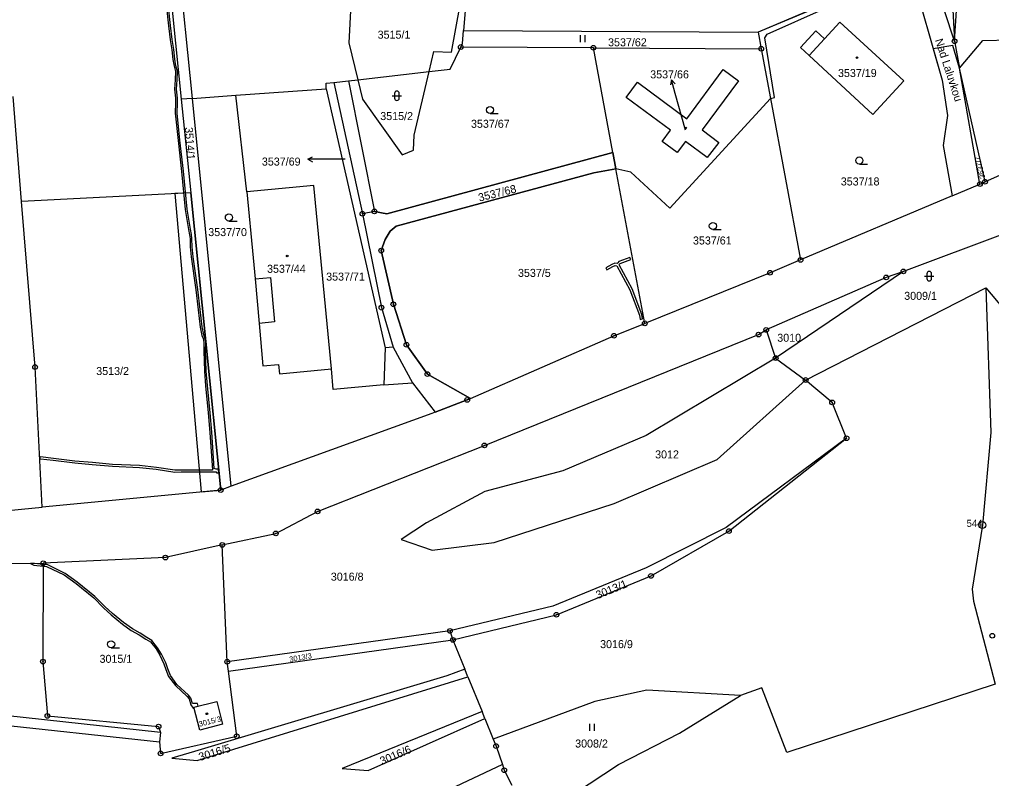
# Model space of a CAD drawing. Extents: x -644096 to -634268, y -1141430 to -1133463.
# Drawn here: x -641396.2 to -641189.8, y -1138498.2 to -1138337.1 of the extents above; entities that cross this region are included whole.
import ezdxf

# ---------------------------------------------------------------- set-up
doc = ezdxf.new("R2010")
doc.units = 0
for name, color, linetype in [('_CIVIL_CONSTRUCTION', 7, 'Continuous'), ('B_Hranice _3D', 7, 'Continuous'), ('M_Svah_Nasyp', 7, 'Continuous'), ('M_Svah_Zarez', 7, 'Continuous'), ('svrsek_osa_sjezdy', 7, 'Continuous'), ('svrsek_osa_VRT', 7, 'Continuous'), ('svrsek_popisy_VRT', 7, 'Continuous'), ('terminal_VRT', 7, 'Continuous')]:
    doc.layers.add(name, color=color, linetype=linetype)

msp = doc.modelspace()

# ---------------------------------------------------------------- linework, layer by layer
at = {"layer": '_CIVIL_CONSTRUCTION'}
for centre, radius in [((-641302.47, -1138342.92), 0.5), ((-641302.47, -1138342.92), 0.0303), ((-641274.31, -1138343.08), 0.5), ((-641274.31, -1138343.08), 0.0303), ((-641238.67, -1138343.28), 0.5), ((-641197.59, -1138341.7), 0.5), ((-641197.59, -1138341.7), 0.0303), ((-641238.67, -1138343.28), 0.0303), ((-641192.21, -1138372.01), 0.5), ((-641192.21, -1138372.01), 0.0303), ((-641191.13, -1138371.53), 0.5), ((-641191.13, -1138371.53), 0.0303), ((-641323.37, -1138378.31), 0.5), ((-641320.81, -1138377.82), 0.5), ((-641320.81, -1138377.82), 0.0303), ((-641323.37, -1138378.31), 0.0303), ((-641319.36, -1138386.15), 0.5), ((-641319.36, -1138386.15), 0.0303), ((-641230.32, -1138388.1), 0.5), ((-641230.32, -1138388.1), 0.0303), ((-641236.79, -1138390.83), 0.5), ((-641208.47, -1138390.55), 0.5), ((-641208.47, -1138390.55), 0.0303), ((-641236.79, -1138390.83), 0.0303), ((-641212.13, -1138391.83), 0.5), ((-641212.13, -1138391.83), 0.0303), ((-641319.32, -1138398.25), 0.5), ((-641319.32, -1138398.25), 0.0303), ((-641316.79, -1138397.53), 0.5), ((-641316.79, -1138397.53), 0.0303), ((-641263.4, -1138401.58), 0.5), ((-641263.4, -1138401.58), 0.0303), ((-641237.61, -1138402.96), 0.5), ((-641237.61, -1138402.96), 0.0303), ((-641269.94, -1138404.22), 0.5), ((-641269.94, -1138404.22), 0.0303), ((-641239.24, -1138403.97), 0.5), ((-641239.24, -1138403.97), 0.0303), ((-641314.01, -1138406.13), 0.5), ((-641314.01, -1138406.13), 0.0303), ((-641235.6, -1138408.96), 0.5), ((-641235.6, -1138408.96), 0.0303), ((-641392.88, -1138410.85), 0.5), ((-641392.88, -1138410.85), 0.0303), ((-641309.56, -1138412.35), 0.5), ((-641309.56, -1138412.35), 0.0303), ((-641229.23, -1138413.61), 0.5), ((-641229.23, -1138413.61), 0.0303), ((-641301.1, -1138417.82), 0.5), ((-641301.1, -1138417.82), 0.0303), ((-641223.6, -1138418.36), 0.5), ((-641223.6, -1138418.36), 0.0303), ((-641220.55, -1138425.96), 0.5), ((-641297.45, -1138427.5), 0.5), ((-641297.45, -1138427.5), 0.0303), ((-641220.55, -1138425.96), 0.0303), ((-641353.45, -1138436.97), 0.5), ((-641353.45, -1138436.97), 0.0303), ((-641332.89, -1138441.49), 0.5), ((-641332.89, -1138441.49), 0.0303), ((-641191.7, -1138444.4), 0.75), ((-641341.76, -1138446.18), 0.5), ((-641341.76, -1138446.18), 0.0303), ((-641245.52, -1138445.68), 0.5), ((-641245.52, -1138445.68), 0.0303), ((-641191.7, -1138444.4), 0.03), ((-641353.13, -1138448.62), 0.5), ((-641353.13, -1138448.62), 0.0303), ((-641391.14, -1138452.52), 0.5), ((-641391.14, -1138452.52), 0.0303), ((-641365.18, -1138451.31), 0.5), ((-641365.18, -1138451.31), 0.0303), ((-641262.07, -1138455.18), 0.5), ((-641262.07, -1138455.18), 0.0303), ((-641282.17, -1138463.44), 0.5), ((-641282.17, -1138463.44), 0.0303), ((-641304.77, -1138466.88), 0.5), ((-641304.77, -1138466.88), 0.0303), ((-641304.14, -1138468.78), 0.5), ((-641304.14, -1138468.78), 0.0303), ((-641189.59, -1138467.89), 0.5), ((-641391.2, -1138473.39), 0.5), ((-641352.07, -1138473.42), 0.5), ((-641391.2, -1138473.39), 0.0303), ((-641352.07, -1138473.42), 0.0303), ((-641390.26, -1138484.92), 0.5), ((-641390.26, -1138484.92), 0.0303), ((-641366.66, -1138487.18), 0.5), ((-641366.66, -1138487.18), 0.0303), ((-641350.05, -1138489.21), 0.5), ((-641350.05, -1138489.21), 0.0303), ((-641294.98, -1138491.33), 0.5), ((-641294.98, -1138491.33), 0.0303), ((-641366.22, -1138492.87), 0.5), ((-641366.22, -1138492.87), 0.0303), ((-641293.23, -1138496.43), 0.5), ((-641293.23, -1138496.43), 0.0303)]:
    msp.add_circle(centre, radius, dxfattribs=at)
at = {"layer": 'B_Hranice _3D'}
for points in [[(-641364.97, -1138334.51), (-641364.53, -1138338.41), (-641364.18, -1138341.38), (-641363.82, -1138343.53), (-641363.62, -1138345.54), (-641363.35, -1138347.02), (-641363.04, -1138348.15), (-641363.13, -1138349.88), (-641363.26, -1138351.89), (-641363.05, -1138353.81), (-641363.05, -1138354.74), (-641363.12, -1138356.99), (-641362.5, -1138362.77), (-641361.79, -1138369.35), (-641360.97, -1138377.42), (-641360.3, -1138381.65), (-641360.06, -1138382.76), (-641359.96, -1138383.64), (-641359.93, -1138385.35), (-641359.73, -1138387.47), (-641358.72, -1138394.44), (-641358.22, -1138398.69), (-641357.79, -1138402.37), (-641357.45, -1138404.15), (-641357.18, -1138404.77), (-641357.03, -1138405.64), (-641357.06, -1138407.4), (-641356.93, -1138411.76), (-641356.66, -1138414.83), (-641356.09, -1138420.59), (-641355.74, -1138424.72), (-641355.2, -1138432.73), (-641361.83, -1138432.71), (-641363.19, -1138432.76), (-641367.1, -1138432.16), (-641370.68, -1138431.77), (-641376.43, -1138431.52), (-641380.71, -1138431.15), (-641384.4, -1138430.8), (-641388.97, -1138430.25), (-641391.75, -1138429.89), (-641391.9, -1138429.97), (-641391.88, -1138430.43), (-641391.69, -1138430.31), (-641389.01, -1138430.65), (-641384.44, -1138431.2), (-641380.75, -1138431.55), (-641376.45, -1138431.92), (-641370.72, -1138432.17), (-641367.16, -1138432.56), (-641363.21, -1138433.16), (-641361.83, -1138433.11), (-641354.36, -1138433.13), (-641354.33, -1138433.34), (-641353.82, -1138433.32), (-641353.9, -1138432.51), (-641354.45, -1138432.55), (-641354.83, -1138432.41)], [(-641354.83, -1138432.41), (-641355.34, -1138424.68), (-641355.69, -1138420.55), (-641356.26, -1138414.79), (-641356.53, -1138411.74), (-641356.66, -1138407.4), (-641356.63, -1138405.6), (-641356.8, -1138404.65), (-641357.07, -1138404.03), (-641357.39, -1138402.31), (-641357.82, -1138398.65), (-641358.32, -1138394.38), (-641359.33, -1138387.43), (-641359.53, -1138385.33), (-641359.56, -1138383.62), (-641359.66, -1138382.7), (-641359.9, -1138381.57), (-641360.57, -1138377.36), (-641361.39, -1138369.31), (-641362.1, -1138362.73), (-641362.72, -1138356.97), (-641362.65, -1138354.74), (-641362.65, -1138353.79), (-641362.86, -1138351.89), (-641362.73, -1138349.9), (-641362.64, -1138348.11), (-641362.95, -1138346.94), (-641363.22, -1138345.48), (-641363.42, -1138343.47), (-641363.78, -1138341.32), (-641364.13, -1138338.37), (-641364.57, -1138334.47)]]:
    msp.add_lwpolyline(points, dxfattribs=at)
for points in [[(-641225.41, -1138333.93), (-641239.32, -1138339.79), (-641238.67, -1138343.28), (-641236.71, -1138353.82), (-641235.85, -1138353.67), (-641237.92, -1138340.99), (-641237.43, -1138340.2), (-641224.98, -1138334.7)], [(-641202.12, -1138343.31), (-641200.22, -1138349.93), (-641199.11, -1138357.49), (-641200.01, -1138363.84), (-641198.13, -1138374.51), (-641192.21, -1138372.01), (-641196.58, -1138347.41), (-641197.94, -1138342.57)], [(-641307.93, -1138420.4), (-641301.1, -1138417.82), (-641300.41, -1138417.52), (-641309.56, -1138412.35), (-641314.01, -1138406.13), (-641316.79, -1138397.53), (-641319.36, -1138386.15), (-641318.5, -1138383.8), (-641317.46, -1138382.02), (-641316.16, -1138380.95), (-641274.21, -1138369.64), (-641269.51, -1138368.81), (-641270.16, -1138365.31), (-641318.15, -1138378.31), (-641320.81, -1138377.82), (-641323.37, -1138378.31), (-641319.32, -1138398.25), (-641316.82, -1138406.62), (-641312.73, -1138414.18)], [(-641353.45, -1138436.97), (-641359.82, -1138373.85), (-641363.23, -1138374.03), (-641357.62, -1138437.37)], [(-641264.35, -1138400.73), (-641263.85, -1138400.65), (-641264.01, -1138399.72), (-641266.1, -1138394.27), (-641268.85, -1138389.17), (-641268.76, -1138389.02), (-641268.62, -1138388.9), (-641266.37, -1138388.03), (-641266.55, -1138387.57), (-641268.88, -1138388.46), (-641269.14, -1138388.7), (-641269.26, -1138388.88), (-641269.74, -1138388.79), (-641270.41, -1138389.08), (-641271.69, -1138389.8), (-641271.45, -1138390.23), (-641270.19, -1138389.53), (-641269.68, -1138389.31), (-641269.3, -1138389.38), (-641266.56, -1138394.48), (-641264.49, -1138399.86)], [(-641393.82, -1138452.54), (-641393.14, -1138452.93), (-641391.14, -1138453.14), (-641391.14, -1138452.74), (-641393.02, -1138452.55), (-641393.05, -1138452.53)], [(-641359.44, -1138482.3), (-641359.8, -1138481.12), (-641360.26, -1138480.5), (-641362.77, -1138478.21), (-641364.15, -1138476.36), (-641364.71, -1138474.93), (-641365.14, -1138473.67), (-641366.03, -1138471.81), (-641366.87, -1138470.43), (-641368.11, -1138468.88), (-641369.11, -1138468.26), (-641370.54, -1138467.34), (-641372.22, -1138466.46), (-641374.09, -1138465.1), (-641376.44, -1138463.14), (-641378.06, -1138461.68), (-641380.16, -1138459.56), (-641383.92, -1138456.49), (-641386.52, -1138454.65), (-641390.33, -1138452.79), (-641391.03, -1138452.75), (-641391.14, -1138452.74), (-641391.14, -1138453.14), (-641391.07, -1138453.15), (-641390.43, -1138453.19), (-641386.72, -1138454.99), (-641384.16, -1138456.81), (-641380.42, -1138459.86), (-641378.34, -1138461.96), (-641376.7, -1138463.44), (-641374.33, -1138465.42), (-641372.44, -1138466.8), (-641370.74, -1138467.68), (-641369.33, -1138468.6), (-641368.37, -1138469.18), (-641367.19, -1138470.65), (-641366.39, -1138471.99), (-641365.52, -1138473.83), (-641365.09, -1138475.07), (-641364.51, -1138476.56), (-641363.07, -1138478.47), (-641360.56, -1138480.78), (-641360.16, -1138481.3), (-641359.78, -1138482.58), (-641359.3, -1138483.25), (-641359.13, -1138483.21), (-641359.17, -1138483.07), (-641358.24, -1138482.84), (-641358.41, -1138482.29)]]:
    msp.add_lwpolyline(points, close=True, dxfattribs=at)
at = {"layer": 'M_Svah_Nasyp'}
for p, q in [((-641228.47, -1138344.7), (-641225.21, -1138341.17)), ((-641346.15, -1138392.16), (-641342.9, -1138391.87)), ((-641342.9, -1138391.87), (-641342, -1138401.27)), ((-641342, -1138401.27), (-641345.28, -1138401.6))]:
    msp.add_line(p, q, dxfattribs=at)
msp.add_lwpolyline([(-641267.32, -1138353.62), (-641264.91, -1138350.38), (-641254.48, -1138358.17), (-641246.74, -1138347.72), (-641243.51, -1138350.11), (-641251.21, -1138360.53), (-641247.7, -1138363.16), (-641250.11, -1138366.41), (-641254.78, -1138362.95), (-641256.54, -1138365.32), (-641259.69, -1138362.99), (-641257.94, -1138360.58), (-641267.32, -1138353.62)], dxfattribs=at)
at = {"layer": 'M_Svah_Zarez'}
for centre in [(-641218.32, -1138345.18), (-641254.7, -1138360.11), (-641339.33, -1138387.28), (-641356.39, -1138484.46)]:
    msp.add_circle(centre, 0.175, dxfattribs=at)
at = {"layer": 'svrsek_osa_sjezdy'}
for p, q in [((-641277.05, -1138341.89), (-641277.05, -1138340.39)), ((-641276.05, -1138341.89), (-641276.05, -1138340.39)), ((-641317.04, -1138353.27), (-641315.04, -1138353.27)), ((-641316.54, -1138352.77), (-641316.54, -1138353.77)), ((-641315.54, -1138353.77), (-641315.54, -1138352.77)), ((-641296.26, -1138357.04), (-641294.51, -1138357.04)), ((-641217.83, -1138367.76), (-641216.08, -1138367.76)), ((-641351.71, -1138379.86), (-641349.96, -1138379.86)), ((-641248.94, -1138381.66), (-641247.19, -1138381.66)), ((-641203.99, -1138391.56), (-641201.99, -1138391.56)), ((-641203.49, -1138391.06), (-641203.49, -1138392.06)), ((-641202.49, -1138392.06), (-641202.49, -1138391.06)), ((-641376.72, -1138470.45), (-641374.97, -1138470.45)), ((-641275.04, -1138488.06), (-641275.04, -1138486.56)), ((-641274.04, -1138488.06), (-641274.04, -1138486.56))]:
    msp.add_line(p, q, dxfattribs=at)
for centre in [(-641296.26, -1138356.29), (-641217.83, -1138367.01), (-641351.71, -1138379.11), (-641248.94, -1138380.91), (-641376.72, -1138469.7)]:
    msp.add_circle(centre, 0.75, dxfattribs=at)
for centre, start, end in [((-641316.04, -1138352.77), 0, 180), ((-641316.04, -1138353.77), 180, 359.9879), ((-641202.99, -1138391.06), 0, 180), ((-641202.99, -1138392.06), 180, 359.9879)]:
    msp.add_arc(centre, 0.5, start, end, dxfattribs=at)
at = {"layer": 'svrsek_popisy_VRT'}
for p, q in [((-641257.69, -1138349.88), (-641257.91, -1138350.98)), ((-641256.91, -1138352.78), (-641257.69, -1138349.88)), ((-641257.69, -1138349.88), (-641256.94, -1138350.72)), ((-641254.76, -1138360.58), (-641256.91, -1138352.78)), ((-641334.97, -1138366.76), (-641333.97, -1138366.26)), ((-641331.97, -1138366.76), (-641334.97, -1138366.76)), ((-641334.97, -1138366.76), (-641333.97, -1138367.26)), ((-641327.02, -1138366.72), (-641331.97, -1138366.76))]:
    msp.add_line(p, q, dxfattribs=at)
at = {"layer": 'terminal_VRT'}
for p, q in [((-641207.08, -1138326.21), (-641239.32, -1138339.79)), ((-641301.88, -1138339.41), (-641239.32, -1138339.79)), ((-641239.32, -1138339.79), (-641238.67, -1138343.28)), ((-641274.31, -1138343.08), (-641302.47, -1138342.92)), ((-641274.31, -1138343.08), (-641238.67, -1138343.28)), ((-641270.16, -1138365.31), (-641274.31, -1138343.08)), ((-641197.59, -1138341.7), (-641196.58, -1138347.41)), ((-641238.67, -1138343.28), (-641236.71, -1138353.82)), ((-641324.33, -1138349.9), (-641309.21, -1138348.15)), ((-641312.4, -1138361.64), (-641309.21, -1138348.15)), ((-641192.21, -1138372.01), (-641196.58, -1138347.41)), ((-641191.13, -1138371.53), (-641196.58, -1138347.41)), ((-641329.46, -1138350.43), (-641326.28, -1138350.13)), ((-641326.28, -1138350.13), (-641324.33, -1138349.9)), ((-641359.45, -1138353.85), (-641350.21, -1138353.17)), ((-641350.21, -1138353.17), (-641331.06, -1138351.77)), ((-641347.88, -1138373.69), (-641350.21, -1138353.17)), ((-641331.06, -1138351.77), (-641318.52, -1138406.76)), ((-641395.74, -1138375.72), (-641397.55, -1138353.43)), ((-641359.45, -1138353.85), (-641361.82, -1138354.02)), ((-641361.82, -1138354.02), (-641359.82, -1138373.85)), ((-641351.2, -1138436.15), (-641359.45, -1138353.85)), ((-641236.71, -1138353.82), (-641230.32, -1138388.1)), ((-641270.16, -1138365.31), (-641269.51, -1138368.81)), ((-641263.4, -1138401.58), (-641269.51, -1138368.81)), ((-641192.21, -1138372.01), (-641191.13, -1138371.53)), ((-641359.82, -1138373.85), (-641395.74, -1138375.72)), ((-641359.82, -1138373.85), (-641353.45, -1138436.97)), ((-641198.13, -1138374.51), (-641192.21, -1138372.01)), ((-641198.13, -1138374.51), (-641230.32, -1138388.1)), ((-641186.69, -1138382.45), (-641208.47, -1138390.55)), ((-641208.47, -1138390.55), (-641235.6, -1138408.96)), ((-641229.23, -1138413.61), (-641190.96, -1138394.04)), ((-641190.96, -1138394.04), (-641187.23, -1138398.51)), ((-641190.96, -1138394.04), (-641189.88, -1138424.76)), ((-641237.61, -1138402.96), (-641235.6, -1138408.96)), ((-641318.52, -1138406.76), (-641318.83, -1138414.66)), ((-641235.6, -1138408.96), (-641229.23, -1138413.61)), ((-641353.45, -1138436.97), (-641391.36, -1138440.59)), ((-641351.2, -1138436.15), (-641353.45, -1138436.97)), ((-641406.81, -1138442.06), (-641391.36, -1138440.59)), ((-641352.07, -1138473.42), (-641353.13, -1138448.62)), ((-641304.77, -1138466.88), (-641352.07, -1138473.42)), ((-641304.77, -1138466.88), (-641304.14, -1138468.78)), ((-641351.8, -1138475.4), (-641304.14, -1138468.78)), ((-641304.14, -1138468.78), (-641301.61, -1138475)), ((-641351.8, -1138475.4), (-641352.07, -1138473.42)), ((-641300.97, -1138476.58), (-641301.61, -1138475)), ((-641300.97, -1138476.58), (-641297.96, -1138484)), ((-641297.35, -1138485.48), (-641297.96, -1138484)), ((-641297.35, -1138485.48), (-641295.58, -1138489.85)), ((-641366.26, -1138488.44), (-641366.48, -1138490.43))]:
    msp.add_line(p, q, dxfattribs=at)
for points in [[(-641197.59, -1138341.7), (-641195.63, -1138311.28), (-641192.16, -1138269.19)], [(-641196.58, -1138347.41), (-641191.59, -1138341.56), (-641173.99, -1138341.13), (-641177.7, -1138295.65), (-641188.26, -1138282.45), (-641192.16, -1138269.19)], [(-641296.67, -1138274.39), (-641298.68, -1138300.29), (-641300.1, -1138318.17), (-641301.88, -1138339.41)], [(-641359.45, -1138353.85), (-641362.46, -1138323.77), (-641364.8, -1138275.19)], [(-641365.97, -1138278.49), (-641364.86, -1138323.83), (-641361.82, -1138354.02)], [(-641201.04, -1138281.97), (-641207.4, -1138286.15), (-641212.8, -1138295.35), (-641206, -1138309.94), (-641199.11, -1138313.8), (-641197.59, -1138341.7)], [(-641197.59, -1138341.7), (-641201.77, -1138328.98), (-641206.23, -1138316.59), (-641209.4, -1138310.55), (-641212.78, -1138302.2), (-641216.06, -1138287.31)], [(-641309.21, -1138348.15), (-641308.19, -1138343.85), (-641304.46, -1138344.04), (-641302.57, -1138333.94), (-641308.83, -1138319.3), (-641319.9, -1138306), (-641325.1, -1138320.22), (-641326.21, -1138342.07), (-641324.33, -1138349.9)], [(-641207.08, -1138326.21), (-641206.98, -1138326.43), (-641200.22, -1138349.93), (-641199.11, -1138357.49), (-641200.01, -1138363.84), (-641198.13, -1138374.51)], [(-641093.65, -1138330.04), (-641101.86, -1138334.78), (-641118.59, -1138340.65), (-641158.89, -1138357.22), (-641191.13, -1138371.53)], [(-641221.95, -1138337.64), (-641208.41, -1138350.12), (-641214.96, -1138357.22), (-641228.47, -1138344.7), (-641230.32, -1138343.02), (-641227.05, -1138339.49), (-641225.21, -1138341.17), (-641221.95, -1138337.64)], [(-641302.47, -1138342.92), (-641302.12, -1138342.17), (-641301.88, -1138339.41)], [(-641309.21, -1138348.15), (-641304.7, -1138347.63), (-641302.47, -1138342.92)], [(-641331.06, -1138351.77), (-641331.08, -1138350.62), (-641329.46, -1138350.43)], [(-641329.46, -1138350.43), (-641323.37, -1138378.31), (-641319.32, -1138398.25), (-641316.82, -1138406.62), (-641318.52, -1138406.76)], [(-641326.28, -1138350.13), (-641320.81, -1138377.82), (-641318.15, -1138378.31), (-641270.16, -1138365.31)], [(-641324.33, -1138349.9), (-641323.35, -1138354), (-641314.9, -1138365.82)], [(-641236.71, -1138353.82), (-641258.05, -1138377.12), (-641266.38, -1138369.5), (-641269.51, -1138368.81)], [(-641314.9, -1138365.82), (-641312.49, -1138364.79), (-641312.4, -1138361.64)], [(-641269.51, -1138368.81), (-641274.21, -1138369.64), (-641316.16, -1138380.95), (-641317.46, -1138382.02), (-641318.5, -1138383.8), (-641319.36, -1138386.15), (-641316.79, -1138397.53), (-641314.01, -1138406.13), (-641309.56, -1138412.35), (-641300.41, -1138417.52)], [(-641329.95, -1138411.25), (-641332.33, -1138386.26), (-641333.65, -1138372.34), (-641347.88, -1138373.69)], [(-641347.88, -1138373.69), (-641346.56, -1138387.67), (-641346.15, -1138392.16), (-641345.28, -1138401.6), (-641344.48, -1138410.58), (-641341.17, -1138410.34), (-641340.96, -1138412.27), (-641329.95, -1138411.25)], [(-641391.36, -1138440.59), (-641392.88, -1138410.85), (-641395.74, -1138375.72)], [(-641230.32, -1138388.1), (-641236.79, -1138390.83), (-641263.4, -1138401.58)], [(-641208.47, -1138390.55), (-641212.13, -1138391.83), (-641237.61, -1138402.96)], [(-641353.13, -1138448.62), (-641341.76, -1138446.18), (-641332.89, -1138441.49), (-641297.45, -1138427.5), (-641239.24, -1138403.97), (-641237.61, -1138402.96)], [(-641300.41, -1138417.52), (-641269.94, -1138404.22), (-641263.4, -1138401.58)], [(-641235.6, -1138408.96), (-641263.07, -1138425.42), (-641280.78, -1138432.91), (-641297.39, -1138437.24), (-641309.72, -1138443.94), (-641315.1, -1138447.43), (-641308.57, -1138449.73), (-641295.37, -1138448.08), (-641269.93, -1138439.81), (-641248.02, -1138430.45), (-641229.23, -1138413.61)], [(-641318.83, -1138414.66), (-641329.56, -1138415.64), (-641329.95, -1138411.25)], [(-641318.83, -1138414.66), (-641312.73, -1138414.18), (-641307.93, -1138420.4)], [(-641220.55, -1138425.96), (-641223.6, -1138418.36), (-641229.23, -1138413.61)], [(-641300.41, -1138417.52), (-641301.1, -1138417.82), (-641307.93, -1138420.4)], [(-641307.93, -1138420.4), (-641308.64, -1138420.7), (-641351.2, -1138436.15)], [(-641189.88, -1138424.76), (-641191.7, -1138444.4), (-641193.87, -1138458.01), (-641193.62, -1138460.56), (-641188.97, -1138478.19)], [(-641220.55, -1138425.96), (-641246.14, -1138444.9), (-641263.1, -1138453.47), (-641282.93, -1138461.6), (-641304.77, -1138466.88)], [(-641304.14, -1138468.78), (-641282.17, -1138463.44), (-641262.07, -1138455.18), (-641245.52, -1138445.68), (-641220.55, -1138425.96)], [(-641353.13, -1138448.62), (-641365.18, -1138451.31), (-641391.14, -1138452.52)], [(-641482.39, -1138453.21), (-641433.72, -1138452.84), (-641391.14, -1138452.52)], [(-641391.14, -1138452.52), (-641391.2, -1138473.39), (-641390.26, -1138484.92), (-641366.66, -1138487.18), (-641366.26, -1138488.44)], [(-641301.61, -1138475), (-641305.4, -1138476.43), (-641359.04, -1138492.45), (-641363.82, -1138493.9), (-641358.46, -1138494.36), (-641300.97, -1138476.58)], [(-641366.48, -1138490.43), (-641366.22, -1138492.87), (-641350.05, -1138489.21), (-641351.8, -1138475.4)], [(-641188.97, -1138478.19), (-641233.23, -1138492.66), (-641238.54, -1138478.95), (-641243.06, -1138480.56)], [(-641243.06, -1138480.56), (-641262.93, -1138479.46), (-641274.03, -1138481.85), (-641295.58, -1138489.85)], [(-641287.44, -1138507.42), (-641268.99, -1138495.2), (-641256, -1138488.58), (-641243.06, -1138480.56)], [(-641359.17, -1138483.07), (-641354.29, -1138481.85), (-641353.05, -1138486.69), (-641357.9, -1138487.93), (-641359.17, -1138483.07)], [(-641366.26, -1138488.44), (-641403.28, -1138484.42), (-641438.93, -1138484.59), (-641438.92, -1138486.59), (-641403.27, -1138486.42), (-641366.48, -1138490.43)], [(-641297.96, -1138484), (-641327.68, -1138496.04), (-641322.11, -1138496.48), (-641297.35, -1138485.48)], [(-641295.58, -1138489.85), (-641294.98, -1138491.33), (-641293.64, -1138495.22)], [(-641293.64, -1138495.22), (-641338.47, -1138516.37), (-641365.46, -1138523.02), (-641408.81, -1138541.87), (-641434.54, -1138559.87), (-641472.18, -1138578.15)], [(-641293.64, -1138495.22), (-641293.23, -1138496.43), (-641291.6, -1138499.63)]]:
    msp.add_lwpolyline(points, dxfattribs=at)

# ---------------------------------------------------------------- texts
at = {"layer": '_CIVIL_CONSTRUCTION'}
msp.add_text('544', height=1.5, dxfattribs=at).set_placement((-641195.04, -1138444.78))
at = {"layer": 'svrsek_osa_VRT'}
for s, p in [('3515/1', (-641320.13, -1138341.15)), ('3537/62', (-641271.19, -1138342.77)), ('3537/66', (-641262.24, -1138349.58)), ('3537/19', (-641222.36, -1138349.29)), ('3515/2', (-641319.57, -1138358.43)), ('3537/67', (-641300.3, -1138360.07)), ('3537/69', (-641344.71, -1138368.09)), ('3537/18', (-641221.77, -1138372.31)), ('3537/70', (-641356.1, -1138383.06)), ('3537/61', (-641253.16, -1138384.84)), ('3537/44', (-641343.61, -1138390.85)), ('3537/5', (-641290.32, -1138391.72)), ('3537/71', (-641331.06, -1138392.51)), ('3009/1', (-641208.3, -1138396.59)), ('3010', (-641235.26, -1138405.49)), ('3513/2', (-641379.89, -1138412.55)), ('3012', (-641261.2, -1138430.25)), ('3016/8', (-641330.07, -1138456.2)), ('3016/9', (-641272.88, -1138470.52)), ('3015/1', (-641379.18, -1138473.64)), ('3008/2', (-641278.18, -1138491.62))]:
    msp.add_text(s, height=1.7, dxfattribs=at).set_placement(p)
for s, height, rotation, p in [('3514/1', 1.7, 274, (-641361.07, -1138359.99)), ('3537/7', 1.14, 104, (-641191.08, -1138370.71)), ('3537/68', 1.7, 14, (-641298.51, -1138375.75)), ('3013/1', 1.698, 22, (-641273.39, -1138460.12)), ('3013/3', 1.14, 10, (-641338.78, -1138473.48)), ('3015/3', 1.14, 14, (-641357.95, -1138487.21)), ('3016/5', 1.7, 17, (-641357.84, -1138494.48)), ('3016/6', 1.7, 23, (-641319.21, -1138495.36))]:
    msp.add_text(s, height=height, rotation=rotation, dxfattribs=at).set_placement(p)
at = {"layer": 'svrsek_popisy_VRT'}
msp.add_text('Nad Laluvkou', height=1.7, rotation=288, dxfattribs=at).set_placement((-641201.78, -1138341.45))

doc.saveas('drawing.dxf')
